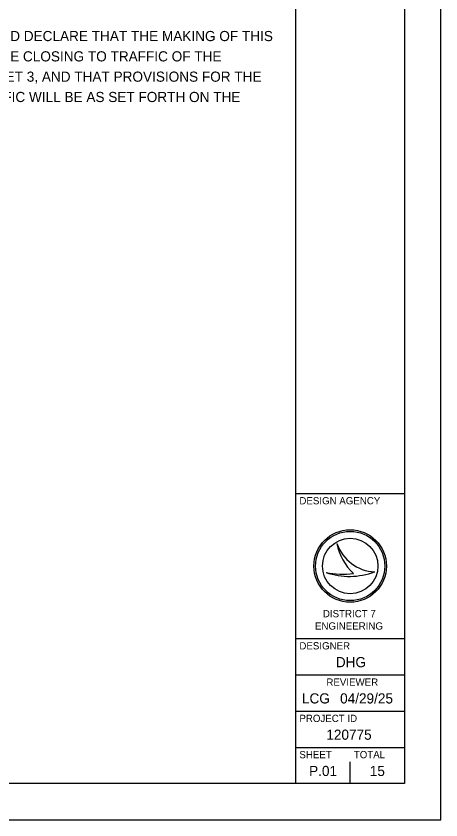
# Model space of a CAD drawing. Extents: x 0 to 34, y 0 to 22.
# Drawn here: x 28.15 to 34, y 0 to 11.08 of the extents above; entities that cross this region are included whole.
import ezdxf

# ---------------------------------------------------------------- set-up
doc = ezdxf.new("R2010")
doc.units = 0
for name, color, linetype in [('SH_Border', 7, 'Continuous'), ('SH_Cut_Line', 7, 'Continuous'), ('SH_Data', 7, 'Continuous'), ('SH_Text', 7, 'Continuous')]:
    doc.layers.add(name, color=color, linetype=linetype)

msp = doc.modelspace()

# ---------------------------------------------------------------- linework, layer by layer
at = {"layer": 'SH_Border'}
for p, q in [((32, 0.5), (32, 21.5)), ((32, 4.5), (33.5, 4.5)), ((32, 2.5), (33.5, 2.5)), ((32, 2), (33.5, 2)), ((32, 1.5), (33.5, 1.5)), ((32, 1), (33.5, 1))]:
    msp.add_line(p, q, dxfattribs=at)
msp.add_lwpolyline([(1.5, 21.5), (33.5, 21.5), (33.5, 0.5), (1.5, 0.5)], close=True, dxfattribs=at)
at = {"layer": 'SH_Cut_Line'}
msp.add_lwpolyline([(0, 0), (34, 0), (34, 22), (0, 22)], close=True, dxfattribs=at)
at = {"layer": 'SH_Data'}
for p, q in [((32.567, 3.81), (32.567, 3.81)), ((32.75, 3.5), (32.75, 3.5)), ((32.417, 3.41), (32.417, 3.41)), ((33.087, 3.419), (33.087, 3.419)), ((32.75, 0.5), (32.75, 0.8)), ((32.375, 0.675), (32.375, 0.675))]:
    msp.add_line(p, q, dxfattribs=at)
for radius in [0.5, 0.477, 0.477, 0.382]:
    msp.add_circle((32.75, 3.5), radius, dxfattribs=at)
for centre, radius, start, end in [((33.116, 3.998), 0.58, 198.9257, 198.9319), ((33.347, 3.97), 0.796, 191.6379, 191.6421), ((33.116, 3.998), 0.58, 198.9319, 267.1657), ((33.347, 3.97), 0.796, 191.6421, 226.0947), ((32.739, 4.37), 1.013, 251.4576, 290.0832), ((32.648, 4.654), 1.266, 259.4964, 259.4995), ((32.739, 4.37), 1.013, 251.4527, 251.4576), ((32.648, 4.654), 1.266, 259.4995, 276.6672)]:
    msp.add_arc(centre, radius, start, end, dxfattribs=at)

# ---------------------------------------------------------------- texts
for s, height, p in [('DESIGN AGENCY', 0.1, (32.05, 4.35)), ('DISTRICT 7', 0.1, (32.374, 2.793)), ('ENGINEERING', 0.1, (32.265, 2.623)), ('DESIGNER', 0.1, (32.05, 2.35)), ('DHG', 0.14, (32.552, 2.105)), ('REVIEWER', 0.1, (32.422, 1.85)), ('LCG', 0.14, (32.085, 1.605)), ('04/29/25', 0.14, (32.611, 1.605)), ('PROJECT ID', 0.1, (32.05, 1.35)), ('120775', 0.14, (32.421, 1.105)), ('SHEET', 0.1, (32.05, 0.85)), ('TOTAL', 0.1, (32.8, 0.85)), ('P.01', 0.14, (32.184, 0.605)), ('15', 0.14, (33.02, 0.605))]:
    msp.add_text(s, height=height, dxfattribs=at).set_placement(p)
at = {"layer": 'SH_Text'}
for s, p in [(' I HEREBY APPROVE THESE PLANS AND DECLARE THAT THE MAKING OF THIS', (24.528, 10.735)), ('IMPROVEMENT WILL NOT REQUIRE THE CLOSING TO TRAFFIC OF THE', (24.528, 10.455)), ('HIGHWAY EXCEPT AS NOTED ON SHEET 3, AND THAT PROVISIONS FOR THE', (24.528, 10.175)), ('MAINTENANCE AND SAFETY OF TRAFFIC WILL BE AS SET FORTH ON THE', (24.528, 9.895))]:
    msp.add_text(s, height=0.14, dxfattribs=at).set_placement(p)

doc.saveas('drawing.dxf')
